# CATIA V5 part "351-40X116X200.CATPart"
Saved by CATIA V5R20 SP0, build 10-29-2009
Part number: 351-40X116X200
Definition: NONE
Nomenclature: 351-40X116X200
Source: Unknown
Description: 351-40X116X200
Bounding box of the stored display mesh (mm): x -8 to 192, y -26 to 26, z -26 to 26
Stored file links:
  C:\Users\Utente\Desktop\IO LAVORO\3D X SITO CF\X SITO\PLASTICA\351\351-40X116X200.CATPart

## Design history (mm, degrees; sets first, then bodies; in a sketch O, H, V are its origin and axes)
Body1 "351-40X116X200" (main body)
  Solid1: solid without history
